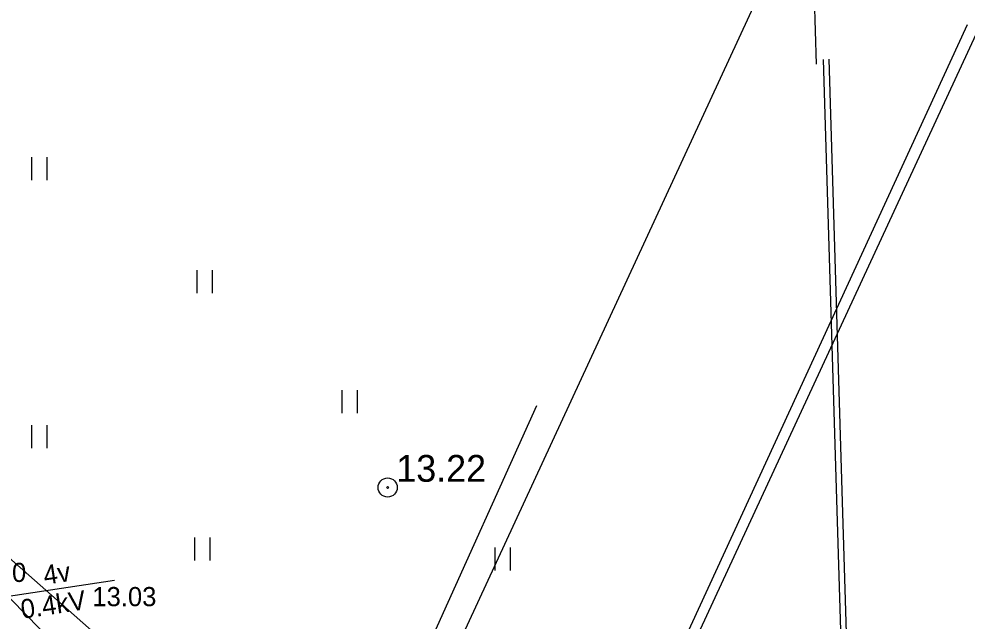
# Model space of a CAD drawing. Extents: x 503877 to 504025, y 304562 to 304725.
# Drawn here: x 503975.24 to 504000, y 304590.57 to 304606.3 of the extents above; entities that cross this region are included whole.
import ezdxf

# ---------------------------------------------------------------- set-up
doc = ezdxf.new("R2010")
doc.units = 0
for name, color, linetype in [('20', 7, 'Continuous'), ('24', 7, 'Continuous'), ('25', 7, 'Continuous'), ('BUVE_ELEM_####_####_#', 7, 'Continuous'), ('ELEK_VADV_ZSPR_####_#', 7, 'Continuous'), ('ELEK_VADV_ZSPR_TKST_#', 7, 'Continuous'), ('Level 46', 7, 'Continuous'), ('NORB_ZOGS_ZSTP_####_#', 7, 'Continuous'), ('RELJ_AATZ_####_TKST_#', 7, 'Continuous'), ('RELJ_HORZ_PAMT_####_#', 7, 'Continuous'), ('SAKT_VADP_KABE_####_#', 7, 'Continuous'), ('TERT_DIAM_####_TKST_#', 7, 'Continuous'), ('TERT_ELEM_####_####_#', 7, 'Continuous')]:
    doc.layers.add(name, color=color, linetype=linetype)

msp = doc.modelspace()

# ---------------------------------------------------------------- linework, layer by layer
at = {"layer": '20'}
msp.add_line((503960.823, 304605.633), (503983.332, 304582.665), dxfattribs=at)
at = {"layer": '24'}
msp.add_line((503987.744, 304578.935), (504010.166, 304627.354), dxfattribs=at)
at = {"layer": '25'}
msp.add_line((503983.332, 304582.665), (504009.636, 304639.466), dxfattribs=at)
at = {"layer": 'BUVE_ELEM_####_####_#'}
for radius in [0.25, 0.0225]:
    msp.add_circle((503984.867, 304594.062), radius, dxfattribs=at)
at = {"layer": 'ELEK_VADV_ZSPR_####_#'}
msp.add_line((503972.501, 304590.85), (503977.734, 304591.644), dxfattribs=at)
at = {"layer": 'Level 46'}
msp.add_line((503943.333, 304620.019), (504006.701, 304564.361), dxfattribs=at)
at = {"layer": 'NORB_ZOGS_ZSTP_####_#'}
for p, q in [((504000, 304606.152), (503994.532, 304594.264)), ((503994.532, 304594.264), (503989.947, 304584.295))]:
    msp.add_line(p, q, dxfattribs=at)
at = {"layer": 'RELJ_HORZ_PAMT_####_#'}
msp.add_line((503984.894, 304587.628), (503988.762, 304596.208), dxfattribs=at)
at = {"layer": 'SAKT_VADP_KABE_####_#'}
msp.add_line((503995.972, 304608.066), (503996.06, 304605.117), dxfattribs=at)
for points in [[(503996.598, 304593.746), (503996.248, 304605.244)], [(503996.759, 304593.401), (503996.398, 304605.249)], [(503997.274, 304571.519), (503996.598, 304593.747)], [(503997.428, 304571.411), (503996.759, 304593.401)]]:
    msp.add_lwpolyline(points, dxfattribs=at)
at = {"layer": 'TERT_ELEM_####_####_#'}
for p, q in [((503975.571, 304602.087), (503975.571, 304602.687)), ((503975.971, 304602.087), (503975.971, 304602.687)), ((503979.893, 304599.139), (503979.893, 304599.739)), ((503980.293, 304599.139), (503980.293, 304599.739)), ((503983.677, 304596.003), (503983.677, 304596.603)), ((503984.077, 304596.003), (503984.077, 304596.603)), ((503975.571, 304595.087), (503975.571, 304595.687)), ((503975.971, 304595.087), (503975.971, 304595.687)), ((503979.833, 304592.155), (503979.833, 304592.755)), ((503980.233, 304592.155), (503980.233, 304592.755)), ((503987.678, 304591.894), (503987.678, 304592.494)), ((503988.078, 304591.894), (503988.078, 304592.494))]:
    msp.add_line(p, q, dxfattribs=at)

# ---------------------------------------------------------------- texts
at = {"layer": 'ELEK_VADV_ZSPR_TKST_#'}
for s, p in [('4v', (503975.912, 304591.519)), ('0.4kV', (503975.323, 304590.629))]:
    msp.add_text(s, height=0.5, rotation=8.6282, dxfattribs=at).set_placement(p)
at = {"layer": 'RELJ_AATZ_####_TKST_#'}
for s, height, p in [('13.22', 0.7, (503985.094, 304594.212)), (' 13.03', 0.5, (503976.968, 304590.962))]:
    msp.add_text(s, height=height, dxfattribs=at).set_placement(p)
at = {"layer": 'TERT_DIAM_####_TKST_#'}
msp.add_text('Li20', height=0.5, dxfattribs=at).set_placement((503974.163, 304591.595))

doc.saveas('drawing.dxf')
